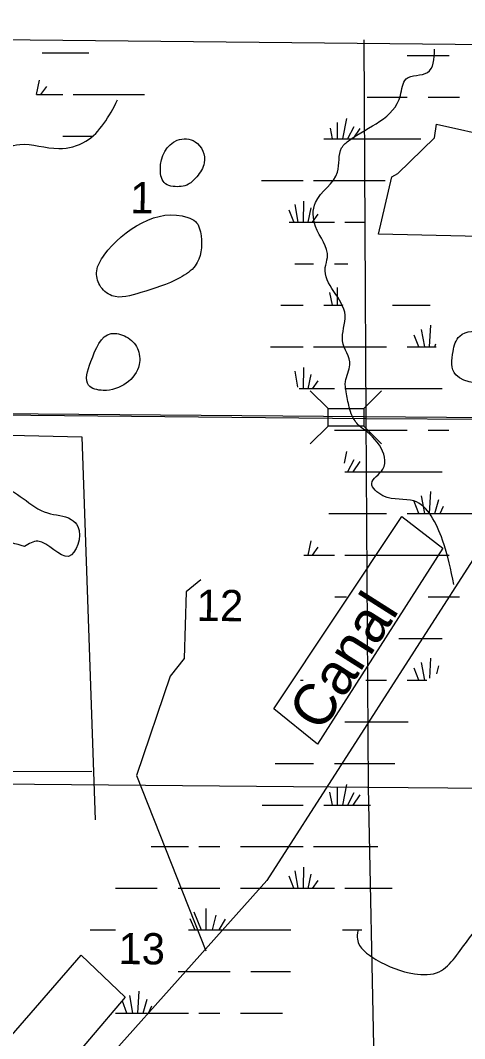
# Model space of a CAD drawing. Extents: x 408847 to 817539, y 923858 to 1151780.
# Drawn here: x 600741 to 607135, y 1030572 to 1045244 of the extents above; entities that cross this region are included whole.
import ezdxf

# ---------------------------------------------------------------- set-up
doc = ezdxf.new("R2010")
doc.units = 0
for name, color, linetype in [('Bridges', 7, 'Continuous'), ('County Boundary', 7, 'Continuous'), ('Lakes and Ponds', 7, 'Continuous'), ('Level 42', 7, 'Continuous'), ('Level 43', 7, 'Continuous'), ('Masks for Text', 7, 'Continuous'), ('Narrow River Creek and Branch and Slough', 7, 'Continuous'), ('Section Lines', 7, 'Continuous'), ('State Routes Highway Center Lines', 7, 'Continuous'), ('Swamps', 7, 'Continuous'), ('Township  and Range lines', 7, 'Continuous')]:
    doc.layers.add(name, color=color, linetype=linetype)

msp = doc.modelspace()

# ---------------------------------------------------------------- linework, layer by layer
at = {"layer": 'Bridges'}
for p, q in [((605170, 1039652), (604914, 1039908)), ((605682, 1039652), (605938, 1039908)), ((605170, 1039396), (604914, 1039140)), ((605682, 1039396), (605938, 1039140))]:
    msp.add_line(p, q, dxfattribs=at)
msp.add_lwpolyline([(605170, 1039652), (605682, 1039652), (605682, 1039396), (605170, 1039396)], close=True, dxfattribs=at)
at = {"layer": 'County Boundary'}
msp.add_line((573707, 1045244), (615573, 1044812), dxfattribs=at)
at = {"layer": 'Lakes and Ponds'}
for points in [[(603280, 1042988), (603388, 1043191), (603257, 1043495), (602999, 1043516), (602755, 1043098), (602829, 1042889), (602938, 1042852), (603159, 1042883), (603280, 1042988)], [(602473, 1041322), (603038, 1041534), (603258, 1041708), (603341, 1042140), (603259, 1042347), (603151, 1042405), (601947, 1041861), (601839, 1041634), (601882, 1041427), (602057, 1041277), (602473, 1041322)], [(601754, 1040328), (601723, 1039986), (601934, 1039912), (602450, 1040283), (602425, 1040517), (602264, 1040685), (602047, 1040730), (601754, 1040328)], [(607471, 1040515), (607396, 1040725), (607064, 1040695), (606969, 1040473), (607008, 1040136), (607497, 1040083), (607449, 1040436), (607471, 1040515)], [(600798, 1037665), (600990, 1037740), (601432, 1037521), (601569, 1037952), (601472, 1038054), (601131, 1038146), (600424, 1038524), (600172, 1038470), (600030, 1038264), (600084, 1037963), (600432, 1037771), (600798, 1037665)]]:
    msp.add_spline(points, degree=3, dxfattribs=at)
at = {"layer": 'Masks for Text'}
for points in [[(604390, 1035322), (606233, 1038093), (606820, 1037640), (605018, 1034817)], [(599071, 1028845), (601615, 1031772), (602251, 1031168), (599675, 1028145)]]:
    msp.add_lwpolyline(points, close=True, dxfattribs=at)
at = {"layer": 'Narrow River Creek and Branch and Slough'}
for p, q in [((607617, 1038041), (604286, 1032849)), ((604286, 1032849), (599482, 1027474))]:
    msp.add_line(p, q, dxfattribs=at)
for points in [[(608611, 1044793), (608496, 1043466), (608182, 1042110), (605896, 1042162), (606085, 1042990), (606175, 1043039), (606703, 1043552), (606731, 1043746), (608449, 1043363)], [(600594, 1039267), (601624, 1039242)], [(601624, 1039242), (601815, 1033723)], [(603337, 1037184), (603127, 1037008), (603096, 1036051), (602898, 1035795), (602410, 1034362), (603409, 1031839)], [(601768, 1034423), (599464, 1034412), (599903, 1037115), (600279, 1037143)]]:
    msp.add_lwpolyline(points, dxfattribs=at)
for points in [[(599569, 1044844), (599485, 1043859), (599740, 1043614), (599702, 1043406), (599699, 1043304), (599958, 1043213), (600733, 1043457), (601296, 1043397), (601681, 1043501), (602140, 1044097)], [(605474, 1039670), (605429, 1039892), (605420, 1040038), (605483, 1040282), (605379, 1040624), (605415, 1040994), (605128, 1041682), (605160, 1041828), (604989, 1042276), (604988, 1042621), (605307, 1043058), (605365, 1043408), (605478, 1043519), (606211, 1044162), (606292, 1044400), (606601, 1044493), (606701, 1044828)], [(605611, 1039405), (605515, 1039546), (605474, 1039670)], [(606979, 1037117), (606818, 1037755), (606404, 1038319), (605959, 1038394), (605799, 1038572), (605959, 1038778), (605909, 1039121), (605611, 1039405)], [(605597, 1032127), (605591, 1032003), (605858, 1031714), (606412, 1031507), (606769, 1031534), (606993, 1031738), (607409, 1032256), (608581, 1032770), (609082, 1032885)]]:
    msp.add_spline(points, degree=3, dxfattribs=at)
at = {"layer": 'Section Lines'}
for p, q in [((600347, 1039560), (605714, 1039508)), ((600358, 1034246), (605735, 1034193)), ((605745, 1034193), (611024, 1034158))]:
    msp.add_line(p, q, dxfattribs=at)
msp.add_lwpolyline([(605714, 1039508), (611024, 1039477)], dxfattribs=at)
at = {"layer": 'State Routes Highway Center Lines'}
for p, q in [((592609, 1039648), (605690, 1039536)), ((605690, 1039536), (609504, 1039503))]:
    msp.add_line(p, q, dxfattribs=at)
at = {"layer": 'Swamps'}
for p, q in [((600974, 1044176), (601017, 1044382)), ((600974, 1044176), (601017, 1044382)), ((600974, 1044176), (601017, 1044382)), ((601036, 1044176), (601120, 1044289)), ((601036, 1044176), (601120, 1044289)), ((601036, 1044176), (601120, 1044289)), ((606610, 1044138), (607060, 1044138)), ((606610, 1044138), (607060, 1044138)), ((606610, 1044138), (607060, 1044138)), ((605434, 1043832), (605375, 1043538)), ((605434, 1043832), (605375, 1043538)), ((605434, 1043832), (605375, 1043538)), ((605542, 1043712), (605448, 1043537)), ((605542, 1043712), (605448, 1043537)), ((605542, 1043712), (605448, 1043537)), ((605627, 1043687), (605528, 1043538)), ((605627, 1043687), (605528, 1043538)), ((605627, 1043687), (605528, 1043538)), ((604510, 1042938), (604810, 1042938)), ((604510, 1042938), (604810, 1042938)), ((604510, 1042938), (604810, 1042938)), ((604816, 1042338), (604822, 1042641)), ((604816, 1042338), (604822, 1042641)), ((604816, 1042338), (604822, 1042641)), ((604675, 1042339), (604609, 1042511)), ((604675, 1042339), (604609, 1042511)), ((604675, 1042339), (604609, 1042511)), ((604738, 1042338), (604698, 1042591)), ((604738, 1042338), (604698, 1042591)), ((604738, 1042338), (604698, 1042591)), ((604883, 1042337), (604926, 1042543)), ((604883, 1042337), (604926, 1042543)), ((604883, 1042337), (604926, 1042543)), ((604945, 1042337), (605029, 1042451)), ((604945, 1042337), (605029, 1042451)), ((604945, 1042337), (605029, 1042451)), ((605192, 1041324), (605229, 1041138)), ((605192, 1041324), (605229, 1041138)), ((605192, 1041324), (605229, 1041138)), ((605301, 1041396), (605301, 1041138)), ((605301, 1041396), (605301, 1041138)), ((605301, 1041396), (605301, 1041138)), ((604510, 1041138), (604810, 1041138)), ((604510, 1041138), (604810, 1041138)), ((604510, 1041138), (604810, 1041138)), ((606631, 1040538), (606648, 1040854)), ((606631, 1040538), (606648, 1040854)), ((606631, 1040538), (606648, 1040854)), ((606475, 1040538), (606410, 1040710)), ((606475, 1040538), (606410, 1040710)), ((606475, 1040538), (606410, 1040710)), ((606560, 1040538), (606514, 1040792)), ((606560, 1040538), (606514, 1040792)), ((606560, 1040538), (606514, 1040792)), ((604510, 1040538), (604810, 1040538)), ((604510, 1040538), (604810, 1040538)), ((604510, 1040538), (604810, 1040538)), ((604960, 1040538), (606010, 1040538)), ((604960, 1040538), (606010, 1040538)), ((604960, 1040538), (606010, 1040538)), ((604816, 1039938), (604822, 1040241)), ((604816, 1039938), (604822, 1040241)), ((604816, 1039938), (604822, 1040241)), ((604883, 1039937), (604926, 1040143)), ((604883, 1039937), (604926, 1040143)), ((604883, 1039937), (604926, 1040143)), ((604945, 1039937), (605029, 1040051)), ((604945, 1039937), (605029, 1040051)), ((604945, 1039937), (605029, 1040051)), ((605260, 1039338), (606310, 1039338)), ((605260, 1039338), (606310, 1039338)), ((605260, 1039338), (606310, 1039338)), ((605542, 1038912), (605448, 1038737)), ((605542, 1038912), (605448, 1038737)), ((605542, 1038912), (605448, 1038737)), ((605627, 1038887), (605528, 1038738)), ((605627, 1038887), (605528, 1038738)), ((605627, 1038887), (605528, 1038738)), ((606560, 1038138), (606514, 1038392)), ((606560, 1038138), (606514, 1038392)), ((606560, 1038138), (606514, 1038392)), ((606631, 1038138), (606648, 1038454)), ((606631, 1038138), (606648, 1038454)), ((606631, 1038138), (606648, 1038454)), ((606475, 1038138), (606410, 1038310)), ((606475, 1038138), (606410, 1038310)), ((606475, 1038138), (606410, 1038310)), ((606708, 1038138), (606766, 1038342)), ((606708, 1038138), (606766, 1038342)), ((606708, 1038138), (606766, 1038342)), ((606784, 1038138), (606833, 1038246)), ((606784, 1038138), (606833, 1038246)), ((606784, 1038138), (606833, 1038246)), ((606310, 1038138), (607360, 1038138)), ((606310, 1038138), (607360, 1038138)), ((606310, 1038138), (607360, 1038138)), ((604945, 1037537), (605029, 1037651)), ((604945, 1037537), (605029, 1037651)), ((604945, 1037537), (605029, 1037651)), ((605410, 1037538), (606910, 1037538)), ((605410, 1037538), (606910, 1037538)), ((605410, 1037538), (606910, 1037538)), ((606610, 1036938), (607060, 1036938)), ((606610, 1036938), (607060, 1036938)), ((606610, 1036938), (607060, 1036938)), ((606186, 1036338), (606810, 1036338)), ((606302, 1036338), (606810, 1036338)), ((606302, 1036338), (606810, 1036338)), ((606475, 1035738), (606410, 1035910)), ((606475, 1035738), (606410, 1035910)), ((606475, 1035738), (606410, 1035910)), ((606560, 1035738), (606514, 1035992)), ((606560, 1035738), (606514, 1035992)), ((606560, 1035738), (606514, 1035992)), ((605713, 1035738), (606010, 1035738)), ((605759, 1035738), (606010, 1035738)), ((605759, 1035738), (606010, 1035738)), ((604510, 1034538), (604960, 1034538)), ((604510, 1034538), (604960, 1034538)), ((604510, 1034538), (604960, 1034538)), ((605192, 1034124), (605229, 1033938)), ((605192, 1034124), (605229, 1033938)), ((605192, 1034124), (605229, 1033938)), ((605301, 1034196), (605301, 1033938)), ((605301, 1034196), (605301, 1033938)), ((605301, 1034196), (605301, 1033938)), ((605434, 1034232), (605375, 1033938)), ((605434, 1034232), (605375, 1033938)), ((605434, 1034232), (605375, 1033938)), ((605542, 1034112), (605448, 1033937)), ((605542, 1034112), (605448, 1033937)), ((605542, 1034112), (605448, 1033937)), ((605627, 1034087), (605528, 1033938)), ((605627, 1034087), (605528, 1033938)), ((605627, 1034087), (605528, 1033938)), ((604510, 1033938), (604810, 1033938)), ((604510, 1033938), (604810, 1033938)), ((604510, 1033938), (604810, 1033938)), ((603310, 1033338), (603610, 1033338)), ((603310, 1033338), (603610, 1033338)), ((603310, 1033338), (603610, 1033338)), ((603910, 1033338), (604510, 1033338)), ((603910, 1033338), (604510, 1033338)), ((603910, 1033338), (604510, 1033338)), ((604510, 1033338), (604810, 1033338)), ((604510, 1033338), (604810, 1033338)), ((604510, 1033338), (604810, 1033338)), ((604738, 1032738), (604698, 1032991)), ((604738, 1032738), (604698, 1032991)), ((604738, 1032738), (604698, 1032991)), ((604816, 1032738), (604822, 1033041)), ((604816, 1032738), (604822, 1033041)), ((604816, 1032738), (604822, 1033041)), ((604883, 1032737), (604926, 1032943)), ((604883, 1032737), (604926, 1032943)), ((604883, 1032737), (604926, 1032943)), ((604675, 1032739), (604609, 1032911)), ((604675, 1032739), (604609, 1032911)), ((604675, 1032739), (604609, 1032911)), ((604945, 1032737), (605029, 1032851)), ((604945, 1032737), (605029, 1032851)), ((604945, 1032737), (605029, 1032851)), ((603010, 1032738), (603610, 1032738)), ((603010, 1032738), (603610, 1032738)), ((603010, 1032738), (603610, 1032738)), ((603910, 1032738), (604510, 1032738)), ((603910, 1032738), (604510, 1032738)), ((603910, 1032738), (604510, 1032738)), ((604510, 1032738), (605260, 1032738)), ((604510, 1032738), (605260, 1032738)), ((604510, 1032738), (605260, 1032738)), ((603239, 1032400), (603342, 1032138)), ((603239, 1032400), (603342, 1032138)), ((603239, 1032400), (603342, 1032138)), ((603408, 1032449), (603408, 1032138)), ((603408, 1032449), (603408, 1032138)), ((603408, 1032449), (603408, 1032138)), ((603553, 1032352), (603500, 1032138)), ((603553, 1032352), (603500, 1032138)), ((603553, 1032352), (603500, 1032138)), ((603179, 1032304), (603250, 1032138)), ((603179, 1032304), (603250, 1032138)), ((603179, 1032304), (603250, 1032138)), ((603686, 1032292), (603596, 1032138)), ((603686, 1032292), (603596, 1032138)), ((603686, 1032292), (603596, 1032138)), ((603160, 1032138), (604510, 1032138)), ((603160, 1032138), (604510, 1032138)), ((603160, 1032138), (604510, 1032138)), ((603010, 1031538), (603760, 1031538)), ((603010, 1031538), (603760, 1031538)), ((603010, 1031538), (603760, 1031538)), ((604060, 1031538), (604510, 1031538)), ((604060, 1031538), (604510, 1031538)), ((604060, 1031538), (604510, 1031538)), ((602360, 1030938), (602314, 1031192)), ((602360, 1030938), (602314, 1031192)), ((602360, 1030938), (602314, 1031192)), ((602431, 1030938), (602448, 1031254)), ((602431, 1030938), (602448, 1031254)), ((602431, 1030938), (602448, 1031254)), ((602275, 1030938), (602210, 1031110)), ((602275, 1030938), (602210, 1031110)), ((602275, 1030938), (602210, 1031110)), ((602508, 1030938), (602566, 1031142)), ((602508, 1030938), (602566, 1031142)), ((602508, 1030938), (602566, 1031142)), ((602584, 1030938), (602633, 1031046)), ((602584, 1030938), (602633, 1031046)), ((602584, 1030938), (602633, 1031046)), ((602110, 1030938), (603160, 1030938)), ((602110, 1030938), (603160, 1030938)), ((602110, 1030938), (603160, 1030938)), ((603310, 1030938), (603610, 1030938)), ((603310, 1030938), (603610, 1030938)), ((603310, 1030938), (603610, 1030938)), ((603910, 1030938), (604510, 1030938)), ((603910, 1030938), (604510, 1030938)), ((603910, 1030938), (604510, 1030938))]:
    msp.add_line(p, q, dxfattribs=at)
for points in [[(601053, 1044776), (601724, 1044776)], [(601053, 1044776), (601724, 1044776)], [(601053, 1044776), (601724, 1044776)], [(606308, 1044738), (606910, 1044738)], [(606308, 1044738), (606910, 1044738)], [(606308, 1044738), (606910, 1044738)], [(600971, 1044176), (601350, 1044176)], [(600971, 1044176), (601350, 1044176)], [(600971, 1044176), (601350, 1044176)], [(601500, 1044176), (602526, 1044176)], [(601500, 1044176), (602526, 1044176)], [(601500, 1044176), (602526, 1044176)], [(605731, 1044138), (606310, 1044138)], [(605731, 1044138), (606310, 1044138)], [(605731, 1044138), (606310, 1044138)], [(605199, 1043690), (605229, 1043538)], [(605199, 1043690), (605229, 1043538)], [(605199, 1043690), (605229, 1043538)], [(605301, 1043773), (605301, 1043538)], [(605301, 1043773), (605301, 1043538)], [(605301, 1043773), (605301, 1043538)], [(601350, 1043576), (601775, 1043576)], [(601350, 1043576), (601775, 1043576)], [(601350, 1043576), (601775, 1043576)], [(605110, 1043538), (606505, 1043538)], [(605110, 1043538), (606505, 1043538)], [(605110, 1043538), (606505, 1043538)], [(604213, 1042938), (604510, 1042938)], [(604213, 1042938), (604510, 1042938)], [(604213, 1042938), (604510, 1042938)], [(604960, 1042938), (605989, 1042938)], [(604960, 1042938), (605989, 1042938)], [(604960, 1042938), (605989, 1042938)], [(604608, 1042338), (605260, 1042338)], [(604608, 1042338), (605260, 1042338)], [(604608, 1042338), (605260, 1042338)], [(605410, 1042338), (605698, 1042338)], [(605410, 1042338), (605698, 1042338)], [(605410, 1042338), (605698, 1042338)], [(604693, 1041738), (604960, 1041738)], [(604693, 1041738), (604960, 1041738)], [(604693, 1041738), (604960, 1041738)], [(605260, 1041738), (605453, 1041738)], [(605260, 1041738), (605453, 1041738)], [(605260, 1041738), (605453, 1041738)], [(605376, 1041147), (605375, 1041138)], [(605376, 1041147), (605375, 1041138)], [(605376, 1041147), (605375, 1041138)], [(604491, 1041138), (604510, 1041138)], [(604491, 1041138), (604510, 1041138)], [(604491, 1041138), (604510, 1041138)], [(605110, 1041138), (605379, 1041138)], [(605110, 1041138), (605379, 1041138)], [(605110, 1041138), (605379, 1041138)], [(606096, 1041138), (606637, 1041138)], [(606096, 1041138), (606637, 1041138)], [(606096, 1041138), (606637, 1041138)], [(606708, 1040538), (606721, 1040583)], [(606708, 1040538), (606721, 1040583)], [(606708, 1040538), (606721, 1040583)], [(604339, 1040538), (604510, 1040538)], [(604339, 1040538), (604510, 1040538)], [(604339, 1040538), (604510, 1040538)], [(606310, 1040538), (606727, 1040538)], [(606310, 1040538), (606727, 1040538)], [(606310, 1040538), (606727, 1040538)], [(604734, 1039960), (604698, 1040191)], [(604734, 1039960), (604698, 1040191)], [(604734, 1039960), (604698, 1040191)], [(604752, 1039938), (605260, 1039938)], [(604752, 1039938), (605260, 1039938)], [(604752, 1039938), (605260, 1039938)], [(605410, 1039938), (606814, 1039938)], [(605410, 1039938), (606814, 1039938)], [(605410, 1039938), (606814, 1039938)], [(606610, 1039338), (606906, 1039338)], [(606610, 1039338), (606906, 1039338)], [(606610, 1039338), (606906, 1039338)], [(605434, 1039032), (605399, 1038862)], [(605434, 1039032), (605399, 1038862)], [(605434, 1039032), (605399, 1038862)], [(605412, 1038738), (606810, 1038738)], [(605412, 1038738), (606810, 1038738)], [(605412, 1038738), (606810, 1038738)], [(605178, 1038138), (606010, 1038138)], [(605178, 1038138), (606010, 1038138)], [(605178, 1038138), (606010, 1038138)], [(604883, 1037537), (604926, 1037743)], [(604883, 1037537), (604926, 1037743)], [(604883, 1037537), (604926, 1037743)], [(604819, 1037538), (605260, 1037538)], [(604819, 1037538), (605260, 1037538)], [(604819, 1037538), (605260, 1037538)], [(605267, 1036938), (605436, 1036938)], [(606633, 1035767), (606648, 1036054)], [(606633, 1035767), (606648, 1036054)], [(606633, 1035767), (606648, 1036054)], [(606734, 1035829), (606766, 1035942)], [(606734, 1035829), (606766, 1035942)], [(606734, 1035829), (606766, 1035942)], [(604771, 1035738), (604810, 1035738)], [(606310, 1035738), (606592, 1035738)], [(606310, 1035738), (606592, 1035738)], [(606310, 1035738), (606592, 1035738)], [(605410, 1035138), (606320, 1035138)], [(605662, 1035138), (606320, 1035138)], [(605662, 1035138), (606320, 1035138)], [(604406, 1034538), (604510, 1034538)], [(604406, 1034538), (604510, 1034538)], [(604406, 1034538), (604510, 1034538)], [(605260, 1034538), (606129, 1034538)], [(605260, 1034538), (606129, 1034538)], [(605260, 1034538), (606129, 1034538)], [(604219, 1033938), (604510, 1033938)], [(604219, 1033938), (604510, 1033938)], [(604219, 1033938), (604510, 1033938)], [(605110, 1033938), (605780, 1033938)], [(605110, 1033938), (605780, 1033938)], [(605110, 1033938), (605780, 1033938)], [(602625, 1033338), (603160, 1033338)], [(602625, 1033338), (603160, 1033338)], [(602625, 1033338), (603160, 1033338)], [(604960, 1033338), (605886, 1033338)], [(604960, 1033338), (605886, 1033338)], [(604960, 1033338), (605886, 1033338)], [(602108, 1032738), (602710, 1032738)], [(602108, 1032738), (602710, 1032738)], [(602108, 1032738), (602710, 1032738)], [(605410, 1032738), (606090, 1032738)], [(605410, 1032738), (606090, 1032738)], [(605410, 1032738), (606090, 1032738)], [(601746, 1032138), (602110, 1032138)], [(601746, 1032138), (602110, 1032138)], [(601746, 1032138), (602110, 1032138)], [(604510, 1032138), (604631, 1032138)], [(604510, 1032138), (604631, 1032138)], [(604510, 1032138), (604631, 1032138)], [(605375, 1032138), (605653, 1032138)], [(605375, 1032138), (605653, 1032138)], [(605375, 1032138), (605653, 1032138)], [(604510, 1031538), (604629, 1031538)], [(604510, 1031538), (604629, 1031538)], [(604510, 1031538), (604629, 1031538)], [(604510, 1030938), (604514, 1030938)], [(604510, 1030938), (604514, 1030938)], [(604510, 1030938), (604514, 1030938)]]:
    msp.add_lwpolyline(points, dxfattribs=at)
at = {"layer": 'Township  and Range lines'}
for p, q in [((605682, 1044965), (605714, 1039508)), ((605714, 1039508), (605745, 1034193)), ((605745, 1034193), (605858, 1028873))]:
    msp.add_line(p, q, dxfattribs=at)

# ---------------------------------------------------------------- texts
at = {"layer": 'Level 42'}
msp.add_text('Canal', height=600, rotation=57.5875, dxfattribs=at).set_placement((605078, 1034973))
at = {"layer": 'Level 43'}
for s, rotation, p in [('1', 359.3791, (602321, 1042466)), ('12', 359.3791, (603276, 1036592)), ('13', 359.379, (602150, 1031647))]:
    msp.add_text(s, height=450, rotation=rotation, dxfattribs=at).set_placement(p)

doc.saveas('drawing.dxf')
